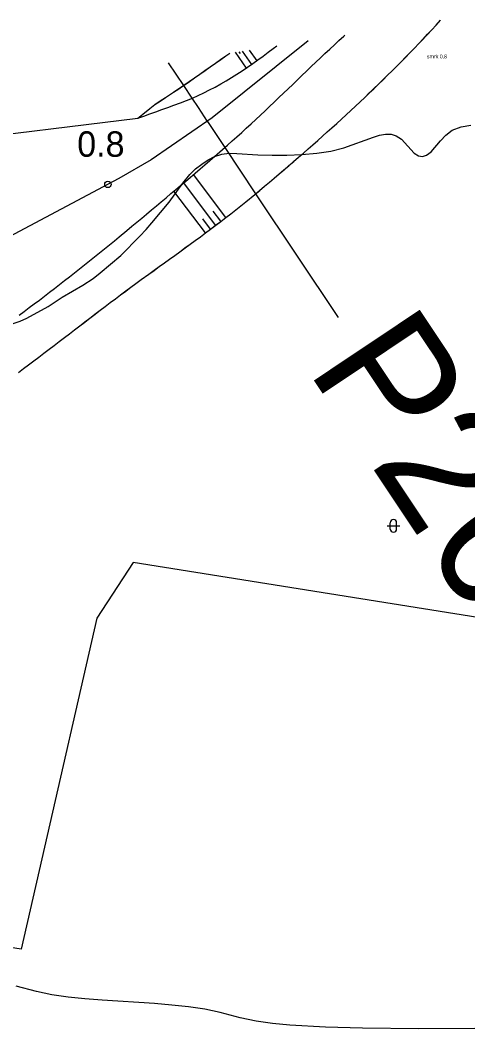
# Model space of a CAD drawing. Extents: x -737422 to -734235, y -1145631 to -1142623.
# Drawn here: x -734943.3 to -734908.1, y -1142867.3 to -1142788.1 of the extents above; entities that cross this region are included whole.
import ezdxf

# ---------------------------------------------------------------- set-up
doc = ezdxf.new("R2010")
doc.units = 0
for name, color, linetype in [('Vrstva 1', 7, 'Continuous'), ('Vrstva 2', 7, 'Continuous'), ('Vrstva 20', 7, 'Continuous'), ('Vrstva 21', 7, 'Continuous'), ('Vrstva 22', 7, 'Continuous'), ('Vrstva 3', 7, 'Continuous'), ('Vrstva 6', 7, 'Continuous'), ('Vrstva 7', 7, 'Continuous'), ('Vrstva 8', 7, 'Continuous'), ('Vrstva 9', 7, 'Continuous')]:
    doc.layers.add(name, color=color, linetype=linetype)

# ---------------------------------------------------------------- blocks, each defined once
blk = doc.blocks.new('1.050')
at = {"layer": 'Vrstva 1'}
for radius in [0.5, 0.001]:
    blk.add_circle((0, 0), radius, dxfattribs=at)
blk = doc.blocks.new('3.160')
at = {"layer": 'Vrstva 1'}
for p, q in [((-1, 0), (1, 0)), ((-0.5, -0.5), (-0.5, 0.5)), ((0.5, -0.5), (0.5, 0.5))]:
    blk.add_line(p, q, dxfattribs=at)
for centre, start, end in [((0, 0.5), 0, 180), ((0, -0.5), 180, 360)]:
    blk.add_arc(centre, 0.5, start, end, dxfattribs=at)

msp = doc.modelspace()

# ---------------------------------------------------------------- linework, layer by layer
at = {"layer": 'Vrstva 1'}
for points in [[(-734915.543, -1142797.276), (-734915.054, -1142797.123), (-734914.597, -1142797.033), (-734914.158, -1142797.044), (-734913.755, -1142797.163), (-734913.344, -1142797.441), (-734912.351, -1142798.532), (-734912.007, -1142798.75), (-734911.69, -1142798.795), (-734911.367, -1142798.705), (-734911.004, -1142798.43), (-734910.275, -1142797.57), (-734909.85, -1142797.117), (-734909.343, -1142796.735), (-734908.658, -1142796.458), (-734907.885, -1142796.34)], [(-734943.853, -1142811.907), (-734943.302, -1142811.74), (-734942.768, -1142811.5), (-734941.114, -1142810.582), (-734939.992, -1142809.85), (-734938.368, -1142808.901), (-734937.572, -1142808.383), (-734937.014, -1142807.948), (-734935.398, -1142806.563), (-734933.901, -1142805.048), (-734933.411, -1142804.536), (-734932.948, -1142804), (-734931.597, -1142802.385), (-734930.531, -1142800.89), (-734929.975, -1142800.21), (-734929.514, -1142799.774), (-734929.029, -1142799.391), (-734928.538, -1142799.054), (-734928.022, -1142798.787), (-734927.465, -1142798.619), (-734926.879, -1142798.547), (-734926.276, -1142798.558), (-734924.618, -1142798.667), (-734923.506, -1142798.696), (-734922.34, -1142798.69), (-734921.157, -1142798.639), (-734919.994, -1142798.536), (-734918.886, -1142798.368), (-734917.875, -1142798.12), (-734915.543, -1142797.276)], [(-734923.469, -1142866.888), (-734924.769, -1142866.704), (-734926.001, -1142866.452), (-734927.588, -1142866.028), (-734928.799, -1142865.777), (-734930.073, -1142865.59), (-734931.393, -1142865.449), (-734932.743, -1142865.339), (-734936.857, -1142865.07), (-734938.209, -1142864.962), (-734939.532, -1142864.822), (-734940.81, -1142864.636), (-734942.025, -1142864.386), (-734943.619, -1142863.961)], [(-734907.574, -1142867.295), (-734911.981, -1142867.318), (-734916.4, -1142867.268), (-734919.3, -1142867.185), (-734922.115, -1142867.022), (-734923.469, -1142866.888)]]:
    msp.add_lwpolyline(points, dxfattribs=at)
at = {"layer": 'Vrstva 2'}
msp.add_lwpolyline([(-734920.664, -1142789.715), (-734928.21, -1142795.76), (-734933.01, -1142799.07), (-734935.54, -1142800.53), (-734990.7, -1142829.83)], dxfattribs=at)
at = {"layer": 'Vrstva 20'}
for points in [[(-734912.67, -1142790.65), (-734912.32, -1142790.29), (-734911.98, -1142789.93), (-734911.63, -1142789.57), (-734911.29, -1142789.2), (-734910.95, -1142788.84), (-734910.61, -1142788.47), (-734910.27, -1142788.1), (-734910.261, -1142788.09)], [(-734943.39, -1142811.27), (-734942.99, -1142810.97), (-734942.59, -1142810.67), (-734942.19, -1142810.37), (-734941.79, -1142810.07), (-734941.39, -1142809.77), (-734941, -1142809.46), (-734940.6, -1142809.16), (-734940.21, -1142808.85), (-734939.81, -1142808.55), (-734939.42, -1142808.24), (-734939.02, -1142807.93), (-734938.63, -1142807.62), (-734938.24, -1142807.31), (-734937.85, -1142806.99), (-734937.46, -1142806.68), (-734937.07, -1142806.37), (-734936.68, -1142806.05), (-734936.29, -1142805.73), (-734935.9, -1142805.42), (-734935.52, -1142805.1), (-734934.91, -1142804.6), (-734934.52, -1142804.28), (-734934.14, -1142803.96), (-734933.75, -1142803.64), (-734933.37, -1142803.32), (-734932.99, -1142803), (-734932.6, -1142802.68), (-734932.22, -1142802.36), (-734931.84, -1142802.04), (-734931.45, -1142801.71), (-734931.07, -1142801.39), (-734930.69, -1142801.07), (-734930.31, -1142800.75), (-734929.93, -1142800.42), (-734929.55, -1142800.1), (-734929.17, -1142799.77), (-734928.79, -1142799.45), (-734928.41, -1142799.12), (-734928.03, -1142798.8), (-734927.39, -1142798.24), (-734927.01, -1142797.91), (-734926.64, -1142797.58), (-734926.27, -1142797.25), (-734925.89, -1142796.91), (-734925.53, -1142796.57), (-734925.16, -1142796.23), (-734924.79, -1142795.89), (-734924.42, -1142795.55), (-734924.06, -1142795.21), (-734923.7, -1142794.86), (-734923.33, -1142794.52), (-734922.97, -1142794.17), (-734922.61, -1142793.83), (-734922.25, -1142793.48), (-734921.88, -1142793.13), (-734921.52, -1142792.78), (-734921.16, -1142792.44), (-734920.8, -1142792.09), (-734920.44, -1142791.74), (-734920.07, -1142791.4), (-734919.71, -1142791.05), (-734919.35, -1142790.71), (-734918.98, -1142790.37), (-734918.61, -1142790.03), (-734918.25, -1142789.69), (-734917.88, -1142789.35), (-734917.788, -1142789.266)], [(-734943.44, -1142815.76), (-734943.04, -1142815.46), (-734942.64, -1142815.16), (-734942.23, -1142814.86), (-734941.83, -1142814.55), (-734941.43, -1142814.25), (-734941.03, -1142813.94), (-734940.63, -1142813.64), (-734940.23, -1142813.33), (-734939.83, -1142813.02), (-734939.43, -1142812.72), (-734939.03, -1142812.41), (-734938.62, -1142812.1), (-734938.22, -1142811.8), (-734937.82, -1142811.49), (-734937.42, -1142811.18), (-734937.02, -1142810.88), (-734936.62, -1142810.57), (-734936.22, -1142810.27), (-734935.82, -1142809.97), (-734935.41, -1142809.67), (-734935.01, -1142809.36), (-734934.61, -1142809.06), (-734934.2, -1142808.77), (-734933.8, -1142808.47), (-734933.19, -1142808.03), (-734932.78, -1142807.74), (-734932.38, -1142807.45), (-734931.97, -1142807.15), (-734931.56, -1142806.86), (-734931.16, -1142806.57), (-734930.75, -1142806.28), (-734930.35, -1142805.98), (-734929.94, -1142805.69), (-734929.54, -1142805.39), (-734929.14, -1142805.1), (-734928.74, -1142804.8), (-734928.34, -1142804.5), (-734927.94, -1142804.2), (-734927.54, -1142803.9), (-734927.14, -1142803.6), (-734926.75, -1142803.29), (-734926.36, -1142802.98), (-734925.96, -1142802.67), (-734925.57, -1142802.36), (-734924.87, -1142801.78), (-734924.48, -1142801.46), (-734924.1, -1142801.14), (-734923.72, -1142800.82), (-734923.33, -1142800.49), (-734922.95, -1142800.17), (-734922.57, -1142799.84), (-734922.19, -1142799.52), (-734921.81, -1142799.19), (-734921.43, -1142798.86), (-734921.05, -1142798.53), (-734920.67, -1142798.2), (-734920.3, -1142797.87), (-734919.92, -1142797.54), (-734919.55, -1142797.21), (-734919.17, -1142796.87), (-734918.8, -1142796.54), (-734918.43, -1142796.2), (-734918.06, -1142795.86), (-734917.69, -1142795.53), (-734917.32, -1142795.19), (-734916.96, -1142794.84), (-734916.59, -1142794.5), (-734916.23, -1142794.16), (-734915.87, -1142793.81), (-734915.51, -1142793.47), (-734915.15, -1142793.12), (-734914.79, -1142792.77), (-734914.43, -1142792.42), (-734914.08, -1142792.07), (-734913.72, -1142791.72), (-734913.37, -1142791.36), (-734913.02, -1142791.01), (-734912.67, -1142790.65)], [(-734934.05, -1142795.79), (-734933.58, -1142795.62), (-734933.11, -1142795.45), (-734932.64, -1142795.28), (-734932.17, -1142795.11), (-734931.7, -1142794.94), (-734931.23, -1142794.77), (-734930.69, -1142794.57), (-734930.22, -1142794.39), (-734929.76, -1142794.21), (-734929.31, -1142794.01), (-734928.86, -1142793.8), (-734928.42, -1142793.57), (-734927.98, -1142793.34), (-734927.54, -1142793.1), (-734927.11, -1142792.86), (-734926.69, -1142792.6), (-734926.27, -1142792.33), (-734925.85, -1142792.06), (-734925.44, -1142791.78), (-734925.02, -1142791.5), (-734924.62, -1142791.21), (-734924.21, -1142790.91), (-734923.81, -1142790.61), (-734923.41, -1142790.31), (-734923.142, -1142790.102)], [(-734934.05, -1142795.79), (-734933.67, -1142795.47), (-734933.12, -1142795.02), (-734932.72, -1142794.72), (-734932.31, -1142794.44), (-734931.89, -1142794.17), (-734931.24, -1142793.75), (-734930.83, -1142793.47), (-734930.42, -1142793.18), (-734930.01, -1142792.9), (-734929.6, -1142792.61), (-734929.19, -1142792.33), (-734928.78, -1142792.04), (-734928.37, -1142791.75), (-734927.96, -1142791.47), (-734927.55, -1142791.18), (-734927.14, -1142790.89), (-734926.831, -1142790.679)], [(-734899.03, -1142841.66), (-734898.63, -1142836.39), (-734934.42, -1142830.68), (-734937.29, -1142835.06), (-734941.61, -1142853.97), (-734943.23, -1142861.05), (-734970.48, -1142856.73), (-735008.81, -1142850.65)]]:
    msp.add_lwpolyline(points, dxfattribs=at)
at = {"layer": 'Vrstva 21'}
for points in [[(-734926.403, -1142790.612), (-734925.53, -1142791.85)], [(-734926.127, -1142790.569), (-734926.02, -1142790.72)], [(-734925.858, -1142790.527), (-734925.12, -1142791.57)], [(-734925.304, -1142790.44), (-734924.71, -1142791.28)], [(-734927.14, -1142803.59), (-734929.69, -1142800.22)], [(-734927.94, -1142804.2), (-734930.45, -1142800.87)], [(-734928.74, -1142804.8), (-734931.22, -1142801.51)], [(-734927.54, -1142803.89), (-734928.14, -1142803.1)], [(-734928.34, -1142804.5), (-734928.94, -1142803.7)]]:
    msp.add_lwpolyline(points, dxfattribs=at)
at = {"layer": 'Vrstva 3'}
for points in [[(-734912.67, -1142790.648), (-734912.323, -1142790.289), (-734911.977, -1142789.929), (-734911.633, -1142789.566), (-734911.29, -1142789.203), (-734910.949, -1142788.837), (-734910.61, -1142788.47), (-734910.272, -1142788.102), (-734910.261, -1142788.09)], [(-734943.444, -1142815.76), (-734943.04, -1142815.459), (-734942.637, -1142815.158), (-734942.234, -1142814.855), (-734941.832, -1142814.551), (-734941.43, -1142814.246), (-734941.028, -1142813.941), (-734940.627, -1142813.635), (-734940.226, -1142813.329), (-734939.826, -1142813.023), (-734939.425, -1142812.716), (-734939.025, -1142812.409), (-734938.624, -1142812.102), (-734938.224, -1142811.796), (-734937.823, -1142811.489), (-734937.422, -1142811.183), (-734937.021, -1142810.878), (-734936.62, -1142810.573), (-734936.218, -1142810.269), (-734935.816, -1142809.966), (-734935.414, -1142809.665), (-734935.01, -1142809.364), (-734934.606, -1142809.064), (-734934.202, -1142808.766), (-734933.796, -1142808.47), (-734933.19, -1142808.03), (-734932.783, -1142807.737), (-734932.376, -1142807.445), (-734931.97, -1142807.152), (-734931.563, -1142806.86), (-734931.158, -1142806.568), (-734930.752, -1142806.275), (-734930.348, -1142805.982), (-734929.944, -1142805.688), (-734929.541, -1142805.393), (-734929.138, -1142805.097), (-734928.737, -1142804.8), (-734928.337, -1142804.501), (-734927.938, -1142804.201), (-734927.54, -1142803.899), (-734927.144, -1142803.595), (-734926.748, -1142803.289), (-734926.355, -1142802.981), (-734925.963, -1142802.67), (-734925.573, -1142802.356), (-734924.87, -1142801.78), (-734924.484, -1142801.459), (-734924.099, -1142801.137), (-734923.715, -1142800.815), (-734923.332, -1142800.491), (-734922.949, -1142800.167), (-734922.567, -1142799.842), (-734922.186, -1142799.516), (-734921.806, -1142799.189), (-734921.427, -1142798.861), (-734921.049, -1142798.532), (-734920.671, -1142798.202), (-734920.295, -1142797.871), (-734919.92, -1142797.539), (-734919.546, -1142797.206), (-734919.172, -1142796.872), (-734918.8, -1142796.537), (-734918.429, -1142796.201), (-734918.06, -1142795.864), (-734917.691, -1142795.525), (-734917.324, -1142795.185), (-734916.958, -1142794.844), (-734916.593, -1142794.502), (-734916.229, -1142794.158), (-734915.867, -1142793.814), (-734915.506, -1142793.467), (-734915.146, -1142793.12), (-734914.788, -1142792.771), (-734914.432, -1142792.421), (-734914.076, -1142792.069), (-734913.723, -1142791.716), (-734913.37, -1142791.362), (-734913.02, -1142791.006), (-734912.67, -1142790.648)], [(-734934.05, -1142795.79), (-734933.665, -1142795.471), (-734933.12, -1142795.02), (-734932.723, -1142794.717), (-734932.308, -1142794.438), (-734931.886, -1142794.169), (-734931.24, -1142793.75), (-734930.828, -1142793.466), (-734930.417, -1142793.182), (-734930.006, -1142792.898), (-734929.595, -1142792.612), (-734929.185, -1142792.327), (-734928.775, -1142792.04), (-734928.365, -1142791.754), (-734927.955, -1142791.467), (-734927.546, -1142791.18), (-734927.137, -1142790.893), (-734926.833, -1142790.679)], [(-734963.99, -1142799.44), (-734934.05, -1142795.79)]]:
    msp.add_lwpolyline(points, dxfattribs=at)
at = {"layer": 'Vrstva 8'}
msp.add_lwpolyline([(-734931.678, -1142791.436), (-734930.48, -1142793.23), (-734929.82, -1142794.21), (-734929.32, -1142794.95), (-734928.61, -1142796.04), (-734928.59, -1142796.06), (-734927.22, -1142798.1), (-734924.81, -1142801.72), (-734918.31, -1142811.45)], dxfattribs=at)

# ---------------------------------------------------------------- block references
at = {"layer": 'Vrstva 20', "xscale": 0.5, "yscale": 0.5}
msp.add_blockref('3.160', (-734913.97, -1142827.81), dxfattribs=at)
at = {"layer": 'Vrstva 6', "xscale": 0.5, "yscale": 0.5}
msp.add_blockref('1.050', (-734936.41, -1142800.99), dxfattribs=at)

# ---------------------------------------------------------------- texts
at = {"layer": 'Vrstva 22'}
msp.add_text('smrk 0,8', height=0.3, dxfattribs=at).set_placement((-734911.34, -1142791.09))
at = {"layer": 'Vrstva 7'}
msp.add_text('0.8', height=2, dxfattribs=at).set_placement((-734938.82, -1142798.82))
at = {"layer": 'Vrstva 9'}
msp.add_text('P26', height=10, rotation=303.744, dxfattribs=at).set_placement((-734920.83, -1142815.48))

doc.saveas('drawing.dxf')
